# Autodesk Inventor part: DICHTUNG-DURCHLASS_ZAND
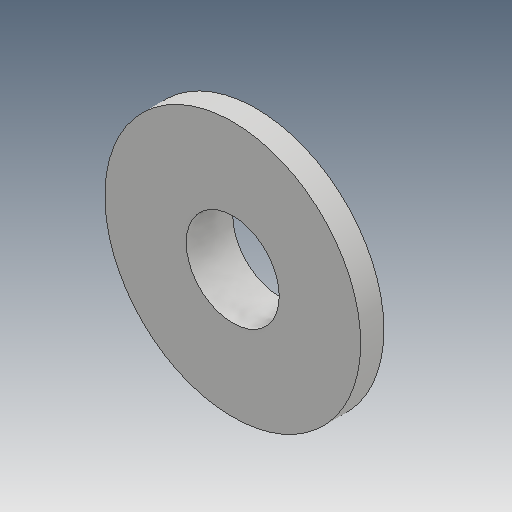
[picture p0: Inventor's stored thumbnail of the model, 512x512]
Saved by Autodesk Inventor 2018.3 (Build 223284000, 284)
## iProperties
Created: 2019-01
Part Number: DICHTUNG-DURCHLASS_ZAND
Material: Generisch
Document SubType Name: Modeling
Designer: zand
Density: 1 g/cm^3
Appearance: Vorgabe
Mass: 0.108385 g
Surface Area: 2.46615 cm^2
Volume: 0.108385 cm^3
Author: zand
Revision Number: 1LAST_VERSION
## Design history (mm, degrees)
feature "Basis1"
node "Volumenkörper1"
